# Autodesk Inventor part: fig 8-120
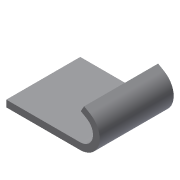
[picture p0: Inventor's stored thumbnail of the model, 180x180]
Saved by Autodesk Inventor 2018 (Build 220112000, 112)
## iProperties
Created: 2009-09
Part Number: fig 8-120
Document SubType Name: Modeling
Designer: Sham
Density: 1 g/cm^3
Material: Generic
Appearance: Default
Author: Sham
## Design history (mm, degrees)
sketch "Sketch1"
  geometry: L1 (-33.976, 22)-(0, 22); L2 (0, 22)-(0, 0); L3 (0, 0)-(-33.976, 0); L4 (-33.976, 0)-(-33.976, 22)
  constraints: 8 end point, 2 parallel, 1 horizontal, 1 perpendicular
extrude "Extrusion1" new body sketch "Sketch1" distance "d0" = 2; taper "d1" = 0 deg
sketch "Sketch2"
  geometry: L1 (-12, 22)-(-12, 0)
  constraints: 2 end point
feature "Bend Part1" sketch "Sketch2" dims "d4" = 10, "d5" = 150 deg
body "Solid1"
